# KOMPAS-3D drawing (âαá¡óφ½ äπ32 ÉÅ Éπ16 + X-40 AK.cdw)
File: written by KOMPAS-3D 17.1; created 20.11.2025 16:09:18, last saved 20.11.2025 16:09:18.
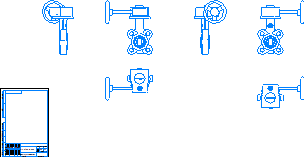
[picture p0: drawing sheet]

Sheet 1: A4, portrait

Title block, sheet 1: name: Гранвэл Ду32; material: Сталь 10  ГОСТ 1050-88; mass: 5,3; sheets: 1; sheet format: A4

Views: Вид 1, Спереди, Проекционный вид 2, Проекционный вид 3, Проекционный вид 4, Проекционный вид 5, Проекционный вид 6
Referenced files in \\adlc.lan\data\АДЛ_ПКД\3D-модели\ADL production\Дисковые поворотные затворы ГРАНВЭЛ\с резьбовыми проушинами с китайским редуктором Ру 16\KOMPAS 3D\: Гранвэл Ду32 РП Ру16 + X-40 AK.m3d
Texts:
  Andrey
  АДЛ
Dimensions and other numbers on the sheet: 1:1; 1; 5,3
